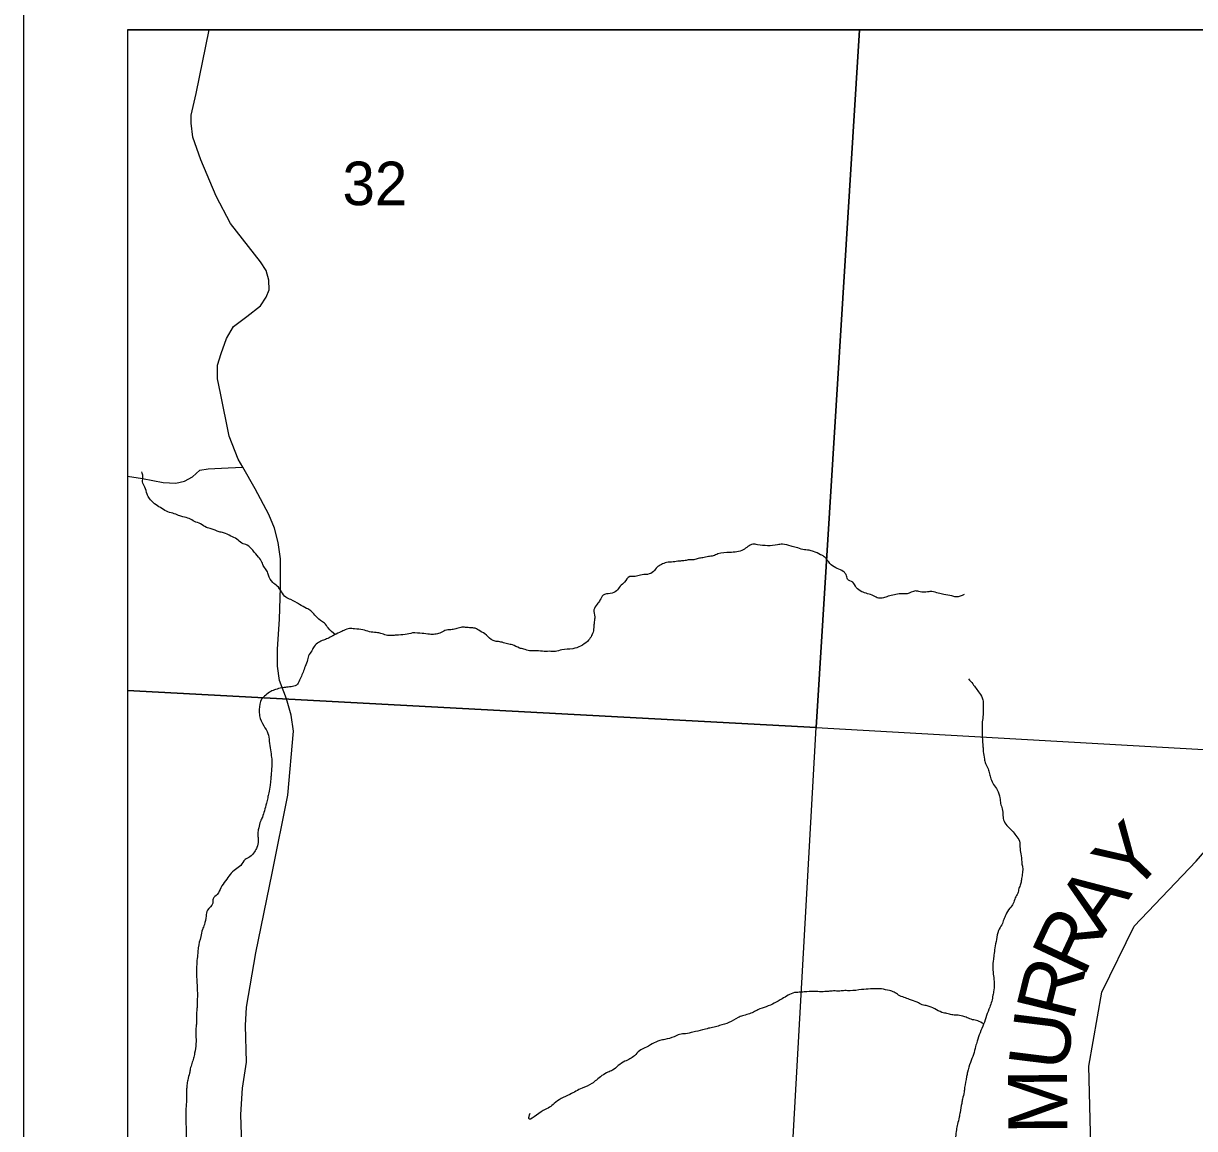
# Model space of a CAD drawing. Extents: x -20.2 to 34, y 0 to 22.
# Drawn here: x 2 to 3.126, y 19.844 to 20.906 of the extents above; entities that cross this region are included whole.
import ezdxf

# ---------------------------------------------------------------- set-up
doc = ezdxf.new("R2010")
doc.units = 0
for name, color, linetype in [('Default', 7, 'Continuous'), ('GM_X_County_Road', 7, 'Continuous'), ('GM_X_Minor_River', 7, 'Continuous'), ('GM_X_Section', 7, 'Continuous'), ('GM_X_Section_Text', 7, 'Continuous'), ('GM_X_Township_Road', 7, 'Continuous'), ('GM_X_Township_Road_Text', 7, 'Continuous'), ('SH_Cut_Line', 7, 'Continuous'), ('SH_Data', 7, 'Continuous')]:
    doc.layers.add(name, color=color, linetype=linetype)

msp = doc.modelspace()

# ---------------------------------------------------------------- linework, layer by layer
at = {"layer": 'Default'}
for points in [[(2.8035, 20.9), (2.1, 20.9), (2.1, 20.265), (2.7621, 20.2295)], [(8.1508, 20.9), (2.1, 20.9), (2.1, 19.2514), (2.9253, 19.1951), (4.084, 19.1299), (4.129, 19.1285), (4.5, 19.1063), (4.5753, 19.1032), (5.0716, 19.0751), (5.6168, 19.0426), (5.628, 19.0419), (5.9006, 19.026), (6.5332, 18.9927), (7.3871, 18.9465), (7.5395, 18.9382), (7.8072, 18.9199), (8.043, 18.9097), (8.0485, 19.0914), (8.0709, 19.4522), (8.1316, 20.5548)], [(3.8628, 20.9), (2.8035, 20.9), (2.7621, 20.2295), (3.8229, 20.1691), (3.8415, 20.5416)], [(2.1, 20.265), (2.1, 19.2427), (2.7046, 19.2077), (2.7621, 20.2295)]]:
    msp.add_lwpolyline(points, close=True, dxfattribs=at)
at = {"layer": 'GM_X_County_Road'}
msp.add_lwpolyline([(2.2098, 19.8283), (2.2091, 19.8575), (2.2106, 19.8829), (2.2143, 19.9079), (2.2136, 19.9429), (2.2145, 19.9606), (2.2235, 20.0129), (2.2392, 20.0893), (2.2543, 20.1644), (2.2595, 20.2259), (2.2573, 20.2412), (2.253, 20.2569), (2.2463, 20.2745), (2.2442, 20.2883), (2.2442, 20.3046), (2.2461, 20.3335), (2.2472, 20.364), (2.2472, 20.3916), (2.245, 20.4071), (2.2412, 20.421), (2.2358, 20.4342), (2.2227, 20.4589), (2.2108, 20.4796), (2.2065, 20.4873), (2.1979, 20.5093), (2.1893, 20.5506), (2.1865, 20.5646), (2.1867, 20.5778), (2.19, 20.5887), (2.1953, 20.6033), (2.202, 20.6147), (2.2147, 20.6244), (2.2278, 20.6347), (2.2333, 20.6429), (2.2362, 20.6502), (2.2358, 20.6592), (2.2332, 20.6687), (2.2278, 20.6769), (2.199, 20.7139), (2.1854, 20.7401), (2.1704, 20.775), (2.1629, 20.7967), (2.1611, 20.8103), (2.1611, 20.8178), (2.1659, 20.8389), (2.1785, 20.9)], dxfattribs=at)
at = {"layer": 'GM_X_Minor_River'}
for points in [[(2.2998, 20.3187), (2.2929, 20.3251), (2.2895, 20.3297), (2.2854, 20.3324), (2.2801, 20.3374), (2.2763, 20.3416), (2.2722, 20.3439), (2.2654, 20.3477), (2.2571, 20.3523), (2.2522, 20.3547), (2.2439, 20.3654), (2.2397, 20.3688), (2.2356, 20.3757), (2.2341, 20.3799), (2.2311, 20.3841), (2.2293, 20.3883), (2.2259, 20.3932), (2.2206, 20.3997), (2.215, 20.4047), (2.21, 20.4066), (2.2051, 20.4105), (2.1995, 20.4132), (2.1923, 20.4166), (2.1881, 20.4174), (2.1805, 20.4205), (2.176, 20.4217), (2.1703, 20.4252), (2.1643, 20.4275), (2.1594, 20.4302), (2.1533, 20.4318), (2.1492, 20.4333), (2.1435, 20.4353), (2.1374, 20.4372), (2.1317, 20.4407), (2.1261, 20.4445), (2.1212, 20.4495), (2.1189, 20.4537), (2.1167, 20.4605), (2.1145, 20.4655), (2.1149, 20.4708), (2.1138, 20.475)], [(2.9044, 20.3572), (2.8964, 20.355), (2.8923, 20.3558), (2.8847, 20.3573), (2.8794, 20.3585), (2.8733, 20.3601), (2.8691, 20.3597), (2.8619, 20.3598), (2.8574, 20.3606), (2.8494, 20.358), (2.8433, 20.358), (2.8372, 20.357), (2.8312, 20.3555), (2.8266, 20.354), (2.822, 20.3537), (2.8171, 20.356), (2.8058, 20.3599), (2.8005, 20.3641), (2.7971, 20.369), (2.7922, 20.3721), (2.7907, 20.3763), (2.7809, 20.3828), (2.7752, 20.3871), (2.7707, 20.3928), (2.7662, 20.3955), (2.7594, 20.3986), (2.7552, 20.3997), (2.7492, 20.4005), (2.7427, 20.4025), (2.7378, 20.4037), (2.7295, 20.4056), (2.7249, 20.4049), (2.7056, 20.4051), (2.701, 20.4055), (2.6919, 20.4002), (2.679, 20.3977), (2.6676, 20.3962), (2.663, 20.3944), (2.6584, 20.3937), (2.6531, 20.3926), (2.6486, 20.3918), (2.6444, 20.3907), (2.6391, 20.3904), (2.6349, 20.3897), (2.6303, 20.3893), (2.6246, 20.3886), (2.6182, 20.3879), (2.6132, 20.386), (2.609, 20.3834), (2.6056, 20.3793), (2.5999, 20.3766), (2.593, 20.3759), (2.5881, 20.3745), (2.5828, 20.3745), (2.5778, 20.3692), (2.5736, 20.3651), (2.5702, 20.3609), (2.5641, 20.3583), (2.5572, 20.3565), (2.5542, 20.3519), (2.5515, 20.3478), (2.5484, 20.3425), (2.5491, 20.3357), (2.5487, 20.3311), (2.5483, 20.3269), (2.5475, 20.3209), (2.5456, 20.3167), (2.5421, 20.3122), (2.5356, 20.3077), (2.528, 20.3051), (2.5174, 20.304), (2.5113, 20.3025), (2.5071, 20.3026), (2.5007, 20.3026), (2.4931, 20.3031), (2.4866, 20.3031), (2.481, 20.3047), (2.4768, 20.3058), (2.47, 20.3089), (2.4654, 20.3097), (2.4601, 20.3113), (2.4556, 20.3121), (2.4514, 20.3129), (2.445, 20.3182), (2.439, 20.3221), (2.4341, 20.3248), (2.4299, 20.3252), (2.425, 20.3256), (2.4204, 20.3256), (2.4155, 20.3242), (2.4109, 20.3234), (2.4052, 20.3227), (2.4003, 20.3201), (2.3953, 20.319), (2.3904, 20.319), (2.3832, 20.3199), (2.3741, 20.3203)], [(2.3741, 20.3203), (2.3669, 20.3188), (2.3585, 20.3181), (2.3539, 20.3178), (2.3486, 20.3182), (2.3437, 20.3198), (2.3392, 20.3206), (2.3327, 20.3214), (2.3263, 20.3233), (2.3183, 20.3242), (2.3134, 20.3246), (2.3081, 20.3227), (2.3039, 20.3208), (2.2974, 20.3175), (2.2925, 20.3149), (2.2883, 20.3134), (2.2837, 20.3111), (2.2795, 20.3074), (2.2772, 20.3032), (2.2741, 20.2983), (2.2726, 20.293), (2.2702, 20.2866), (2.2683, 20.2813), (2.266, 20.2763), (2.2633, 20.271), (2.2587, 20.2688), (2.253, 20.2681), (2.2481, 20.2674), (2.2424, 20.2659), (2.2378, 20.264), (2.2329, 20.2606), (2.229, 20.2565), (2.2267, 20.2466), (2.227, 20.2406), (2.2311, 20.231), (2.2349, 20.2238), (2.2363, 20.2162), (2.2374, 20.2078), (2.2385, 20.2006), (2.2388, 20.1949), (2.2384, 20.1885), (2.238, 20.1831), (2.2376, 20.1782), (2.2371, 20.174), (2.2359, 20.1665), (2.2348, 20.1619), (2.2336, 20.1566), (2.2316, 20.1494), (2.2297, 20.1433), (2.2278, 20.1392), (2.2262, 20.1331), (2.2254, 20.1289), (2.2254, 20.1248), (2.2257, 20.1206), (2.2245, 20.1141), (2.2222, 20.11), (2.2177, 20.1051), (2.2131, 20.1025), (2.2089, 20.0968), (2.2039, 20.093), (2.1986, 20.0881), (2.1943, 20.0821), (2.1897, 20.0753), (2.1863, 20.0689), (2.1824, 20.0647), (2.182, 20.0606), (2.177, 20.0538), (2.1755, 20.0481), (2.1739, 20.0401), (2.172, 20.0352), (2.1704, 20.0284), (2.168, 20.0178), (2.1676, 20.0124), (2.1668, 20.0056), (2.1664, 19.9976), (2.1663, 19.992), (2.1667, 19.9863), (2.167, 19.9771), (2.1673, 19.9722), (2.1669, 19.965), (2.1669, 19.9604), (2.1665, 19.9559), (2.1664, 19.9464), (2.166, 19.9422), (2.1658, 19.9255), (2.1646, 19.9164), (2.1635, 19.9115), (2.1619, 19.9066), (2.1604, 19.9012), (2.1596, 19.8971), (2.158, 19.8906), (2.1572, 19.8857), (2.1568, 19.8808), (2.1567, 19.8701), (2.1563, 19.8652), (2.1562, 19.8489), (2.1565, 19.8439)], [(2.9084, 20.2763), (2.9125, 20.2713), (2.9189, 20.2625), (2.9222, 20.2561), (2.9226, 20.25), (2.9225, 20.2416), (2.9217, 20.2348), (2.9216, 20.2253), (2.9216, 20.2211), (2.9219, 20.2162), (2.9223, 20.2109), (2.9226, 20.2063), (2.9237, 20.1991), (2.9248, 20.1949), (2.9274, 20.1896), (2.9285, 20.185), (2.93, 20.1801), (2.9326, 20.1747), (2.936, 20.1694), (2.9386, 20.1618), (2.9393, 20.1564), (2.9408, 20.1511), (2.9415, 20.1447), (2.9426, 20.1393), (2.9464, 20.134), (2.9505, 20.1302), (2.9539, 20.1256), (2.9573, 20.1202), (2.958, 20.113), (2.9591, 20.1062), (2.9598, 20.0982), (2.9605, 20.094), (2.9601, 20.0883), (2.9593, 20.083), (2.9585, 20.0788), (2.9569, 20.0747), (2.9558, 20.0701), (2.9534, 20.0656), (2.9515, 20.0603), (2.9481, 20.0557), (2.9442, 20.0493), (2.9423, 20.0448), (2.9404, 20.0399), (2.9373, 20.0342), (2.9353, 20.0258), (2.9337, 20.0175), (2.9329, 20.0107), (2.9321, 20.005), (2.932, 19.994), (2.9328, 19.9875), (2.9327, 19.9769), (2.9319, 19.972), (2.9307, 19.9663), (2.9288, 19.9606), (2.9257, 19.9526), (2.9229, 19.9443), (2.9195, 19.936), (2.9168, 19.928), (2.9152, 19.9227), (2.9132, 19.9151), (2.9102, 19.9076), (2.9074, 19.8981), (2.9066, 19.8939), (2.9047, 19.8833), (2.9042, 19.8791), (2.9027, 19.8723), (2.9019, 19.8682), (2.9003, 19.8594), (2.8995, 19.8549), (2.8979, 19.8481), (2.8968, 19.8427), (2.896, 19.8359), (2.8948, 19.8295), (2.8932, 19.8234), (2.8924, 19.8192), (2.8916, 19.8132), (2.8908, 19.8079), (2.8908, 19.8022), (2.8904, 19.798), (2.8907, 19.7908), (2.891, 19.7866), (2.8914, 19.7801), (2.8929, 19.776), (2.8955, 19.7714), (2.8977, 19.7657), (2.9003, 19.7615), (2.9029, 19.7546), (2.9055, 19.7481), (2.9063, 19.744), (2.907, 19.7379), (2.9085, 19.7333), (2.9084, 19.7215), (2.9072, 19.7166), (2.9057, 19.7124), (2.9049, 19.7079), (2.9029, 19.7018), (2.9017, 19.6958)], [(2.923, 19.9445), (2.9173, 19.9474), (2.9124, 19.9486), (2.9071, 19.9505), (2.9029, 19.9521), (2.8968, 19.9529), (2.8923, 19.9533), (2.8877, 19.9545), (2.8828, 19.9556), (2.876, 19.9591), (2.8688, 19.9618), (2.8639, 19.963), (2.859, 19.9653), (2.8518, 19.968), (2.8465, 19.97), (2.8412, 19.9723), (2.837, 19.975), (2.8325, 19.9765), (2.8249, 19.9781), (2.8143, 19.9782), (2.8056, 19.9775), (2.7946, 19.9764), (2.7896, 19.9765), (2.7847, 19.9761), (2.7786, 19.9762), (2.7737, 19.9758), (2.7669, 19.9755), (2.76, 19.9756), (2.7505, 19.9753), (2.7456, 19.9749), (2.7411, 19.9746), (2.735, 19.972), (2.7292, 19.9686), (2.714, 19.9611), (2.706, 19.9581), (2.7018, 19.9559), (2.6912, 19.9522), (2.687, 19.9507), (2.6782, 19.9458), (2.6691, 19.9429), (2.6638, 19.9414), (2.6585, 19.9403), (2.6528, 19.9388), (2.6436, 19.9366), (2.6364, 19.9351), (2.6307, 19.9344), (2.6254, 19.9322), (2.6166, 19.9296), (2.6117, 19.9285), (2.5972, 19.9214), (2.5923, 19.9188), (2.5873, 19.9139), (2.5782, 19.9086), (2.5717, 19.9045), (2.5663, 19.9), (2.5618, 19.8981), (2.5561, 19.8948), (2.5507, 19.8906), (2.5465, 19.8872), (2.537, 19.8828), (2.5252, 19.8768), (2.5168, 19.8727), (2.5103, 19.8682), (2.5057, 19.8644), (2.4997, 19.8614), (2.4859, 19.8535), (2.4871, 19.8588)], [(2.1565, 19.8439), (2.1564, 19.8344), (2.156, 19.8261), (2.1556, 19.8193), (2.1551, 19.8132), (2.1547, 19.8083), (2.1547, 19.8026), (2.1543, 19.7973), (2.1538, 19.7927), (2.1546, 19.7866), (2.156, 19.7809), (2.1575, 19.7752), (2.1579, 19.7706), (2.1597, 19.7657), (2.1639, 19.7603), (2.1653, 19.7554), (2.1672, 19.7489), (2.1709, 19.7436), (2.1743, 19.7386), (2.1781, 19.734), (2.1833, 19.7291), (2.1935, 19.7187), (2.2003, 19.7115), (2.2048, 19.7091), (2.2094, 19.7065), (2.2162, 19.7018), (2.2207, 19.6995), (2.2279, 19.6964), (2.2335, 19.6934), (2.2381, 19.6914), (2.2437, 19.6872), (2.252, 19.6799), (2.2566, 19.6765), (2.2611, 19.6685), (2.2659, 19.6608), (2.2704, 19.6551), (2.2738, 19.6505), (2.278, 19.6467), (2.2832, 19.641), (2.2855, 19.6364), (2.2915, 19.6303), (2.2972, 19.6238), (2.302, 19.618), (2.3062, 19.6142), (2.3107, 19.6088), (2.3149, 19.6058), (2.3201, 19.6019), (2.3273, 19.5958), (2.3307, 19.5916), (2.3348, 19.5866), (2.3382, 19.5813), (2.3408, 19.5763), (2.3438, 19.5687), (2.346, 19.5622), (2.3471, 19.5562), (2.3493, 19.5508), (2.3508, 19.5466), (2.3527, 19.5424), (2.3546, 19.5364), (2.3564, 19.5318), (2.3583, 19.5268), (2.3598, 19.5219), (2.3612, 19.5154), (2.3623, 19.5109), (2.3646, 19.5051), (2.3645, 19.4994)]]:
    msp.add_spline(points, degree=3, dxfattribs=at)
at = {"layer": 'GM_X_Section'}
msp.add_lwpolyline([(3.8229, 20.1691), (3.7661, 19.1519), (2.7046, 19.2077), (2.7621, 20.2295)], close=True, dxfattribs=at)
at = {"layer": 'GM_X_Township_Road'}
for points in [[(2.1, 20.471), (2.1, 20.471), (2.1144, 20.4688), (2.1344, 20.4648), (2.1465, 20.4641), (2.1547, 20.4663), (2.1626, 20.4703), (2.1697, 20.4766), (2.1775, 20.4781), (2.1969, 20.4791), (2.2108, 20.4796)], [(2.971, 19.502), (2.9721, 19.5068), (2.988, 19.5479), (2.9923, 19.5921), (3.0168, 19.6706), (3.0287, 19.752), (3.0262, 19.8146), (3.0241, 19.9038), (3.0367, 19.975), (3.0678, 20.0386), (3.1273, 20.1008), (3.1647, 20.1442), (3.2042, 20.2092), (3.2187, 20.2804), (3.2213, 20.3428), (3.2214, 20.3445), (3.2271, 20.3734)]]:
    msp.add_lwpolyline(points, dxfattribs=at)
at = {"layer": 'SH_Cut_Line'}
msp.add_lwpolyline([(5.7735, 14.1), (8.9, 14.1), (8.9, 20.9), (2.1, 20.9), (2.1, 14.1), (5.3953, 14.1), (5.7268, 14.1076)], close=True, dxfattribs=at)
at = {"layer": 'SH_Data'}
for p, q in [((2, 21), (2, 14)), ((2.1, 20.9), (2.1, 14.1)), ((2.1, 20.9), (8.9, 20.9))]:
    msp.add_line(p, q, dxfattribs=at)

# ---------------------------------------------------------------- texts
at = {"layer": 'GM_X_Section_Text'}
msp.add_text('32', height=0.04186, rotation=0, dxfattribs=at).set_placement((2.3067, 20.7314))
at = {"layer": 'GM_X_Township_Road_Text'}
for s, rotation, p in [('Y', 46.3292, (3.0648, 20.0678)), ('A', 55.1187, (3.0376, 20.0285)), ('R', 64.889, (3.0191, 19.9885)), ('R', 76.0262, (3.0088, 19.9459)), ('U', 82.8967, (3.003, 19.8981)), ('M', 90.3515, (3.0035, 19.8384))]:
    msp.add_text(s, height=0.0568, rotation=rotation, dxfattribs=at).set_placement(p)

doc.saveas('drawing.dxf')
